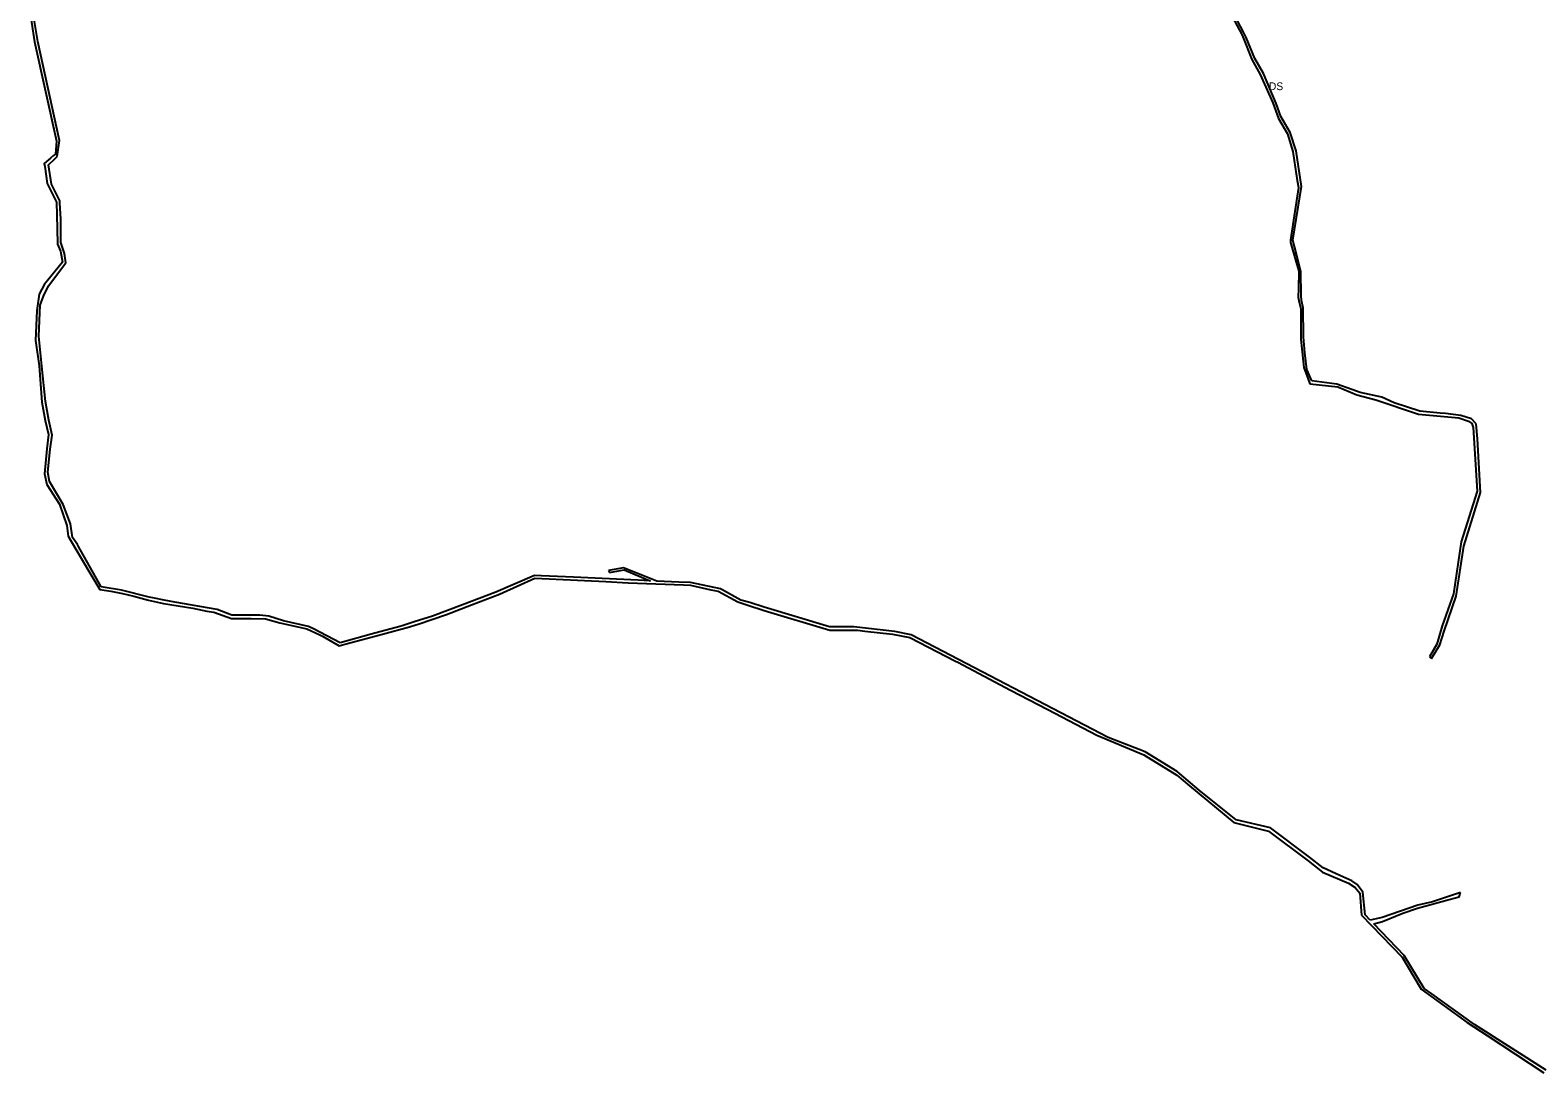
# Model space of a CAD drawing. Extents: x -477304 to -465641, y -1159113 to -1149285.
# Drawn here: x -474185 to -472433, y -1158544 to -1157333 of the extents above; entities that cross this region are included whole.
import ezdxf

# ---------------------------------------------------------------- set-up
doc = ezdxf.new("R2010")
doc.units = 0
doc.layers.add('35', color=7, linetype='Continuous')

msp = doc.modelspace()

# ---------------------------------------------------------------- linework, layer by layer
at = {"layer": '35'}
for p, q in [((-472809, -1157278.8), (-472777.1, -1157338.1)), ((-474184.8, -1157313.7), (-474179.7, -1157346.8)), ((-474175.7, -1157346.4), (-474181.1, -1157313.9)), ((-474150.5, -1157461.2), (-474175.7, -1157346.4)), ((-472777.1, -1157338.1), (-472776, -1157340.8)), ((-472762, -1157366), (-472772.2, -1157341.6)), ((-472752, -1157383.6), (-472762, -1157366)), ((-472737.3, -1157418.4), (-472752, -1157383.6)), ((-472741.4, -1157417.6), (-472736.2, -1157431.5)), ((-472731.8, -1157433.5), (-472737.3, -1157418.4)), ((-472736.2, -1157431.5), (-472734.6, -1157435.7)), ((-474153.3, -1157479.7), (-474150.5, -1157461.2)), ((-474167.8, -1157491.6), (-474165.1, -1157511.4)), ((-474160, -1157511.9), (-474163.3, -1157489.5)), ((-474157.5, -1157478.7), (-474161, -1157481.7)), ((-472716.4, -1157484.5), (-472713.2, -1157507.6)), ((-474165.1, -1157511.4), (-474154.1, -1157532.8)), ((-474149.2, -1157552.7), (-474150.2, -1157533.9)), ((-474149.2, -1157579.6), (-474149.2, -1157552.7)), ((-474144.7, -1157592.4), (-474149.2, -1157579.6)), ((-472716.1, -1157584.6), (-472718, -1157577.1)), ((-474152.9, -1157581.9), (-474149.6, -1157589.8)), ((-474143.3, -1157603.4), (-474144.7, -1157592.4)), ((-472713.4, -1157594.9), (-472716.1, -1157584.6)), ((-472708.7, -1157613.4), (-472713.4, -1157594.9)), ((-474163.5, -1157630.2), (-474143.3, -1157603.4)), ((-472714, -1157602.5), (-472711, -1157613)), ((-472711, -1157613), (-472711.4, -1157633.2)), ((-472708.2, -1157641.2), (-472708.7, -1157613.4)), ((-474169.4, -1157642), (-474163.5, -1157630.2)), ((-474164.3, -1157623.5), (-474167.9, -1157628.3)), ((-472711.4, -1157633.2), (-472711.8, -1157643.2)), ((-474173, -1157652.5), (-474169.4, -1157642)), ((-472711.8, -1157643.2), (-472710.5, -1157649.1)), ((-472710.5, -1157649.1), (-472708.9, -1157657)), ((-472708, -1157647.1), (-472708.2, -1157641.2)), ((-474177.1, -1157658.6), (-474178.5, -1157693.8)), ((-474178.5, -1157693.8), (-474174.4, -1157722.9)), ((-474174.4, -1157722.9), (-474171, -1157765.3)), ((-472698.2, -1157744), (-472665.6, -1157747.5)), ((-472667.1, -1157744.4), (-472695.9, -1157740.5)), ((-472649.7, -1157750.7), (-472667.1, -1157744.4)), ((-474159.1, -1157803.8), (-474163.1, -1157786.1)), ((-472525.2, -1157783.6), (-472513.8, -1157787.5)), ((-472503.5, -1157808), (-472504.9, -1157790.5)), ((-474161.6, -1157819.8), (-474159.1, -1157803.8)), ((-474168.2, -1157848.7), (-474165.2, -1157861)), ((-474165.2, -1157861), (-474150.8, -1157883.7)), ((-474137.7, -1157906.7), (-474146.3, -1157884)), ((-474135.7, -1157922.4), (-474137.7, -1157906.7)), ((-474129.8, -1157930.7), (-474135.7, -1157922.4)), ((-474128.5, -1157933), (-474129.8, -1157930.7)), ((-474102.1, -1157979.9), (-474128.5, -1157933)), ((-473512.9, -1157960.9), (-473511.8, -1157963.3)), ((-474078.8, -1157983.6), (-474102.1, -1157979.9)), ((-474046.5, -1157991.9), (-474078.8, -1157983.6)), ((-473553.6, -1157968.7), (-473590.6, -1157966.9)), ((-473478.5, -1157972.1), (-473553.6, -1157968.7)), ((-473431.4, -1157974.3), (-473456.9, -1157973.4)), ((-473417.8, -1157974.7), (-473431.4, -1157974.3)), ((-474040.4, -1157993.1), (-474046.5, -1157991.9)), ((-474029, -1157995.3), (-474040.4, -1157993.1)), ((-474016.7, -1157997.6), (-474029, -1157995.3)), ((-473967.7, -1158006.3), (-474016.7, -1157997.6)), ((-473682.4, -1158000.9), (-473717.3, -1158013.9)), ((-473643.7, -1157985.9), (-473682.4, -1158000.9)), ((-473348.9, -1157998.2), (-473359.4, -1157995.3)), ((-473332.1, -1158003.6), (-473348.9, -1157998.2)), ((-472531.6, -1157988), (-472544.4, -1158025.1)), ((-473950.5, -1158012.6), (-473967.7, -1158006.3)), ((-473918, -1158012.9), (-473950.5, -1158012.6)), ((-473717.3, -1158013.9), (-473738.6, -1158020.6)), ((-473256.4, -1158026.3), (-473332.1, -1158003.6)), ((-473788.7, -1158035), (-473824.8, -1158045)), ((-473738.6, -1158020.6), (-473752.8, -1158025)), ((-473228, -1158026.2), (-473256.4, -1158026.3)), ((-473180.4, -1158031.7), (-473228, -1158026.2)), ((-472559.4, -1158061.2), (-472557.1, -1158062.9)), ((-472645.6, -1158329.2), (-472643.8, -1158331.6)), ((-472643.8, -1158331.6), (-472640.4, -1158335.9)), ((-472640.4, -1158335.9), (-472638.4, -1158361.4)), ((-472572.7, -1158349.6), (-472614.2, -1158364.1)), ((-472573.2, -1158353.1), (-472536.5, -1158343.1)), ((-472638.4, -1158361.4), (-472591.1, -1158410)), ((-472628.4, -1158366.9), (-472634.1, -1158360.9)), ((-472614.2, -1158364.1), (-472628.4, -1158366.9)), ((-472591.1, -1158410), (-472585, -1158420.7)), ((-472556.7, -1158452.7), (-472565.6, -1158446.3)), ((-472515.5, -1158486.1), (-472492.5, -1158501.2)), ((-472492.5, -1158501.2), (-472426.3, -1158544.5))]:
    msp.add_line(p, q, dxfattribs=at)
for points in [[(-472772.2, -1157341.6), (-472775.2, -1157335.3), (-472805.8, -1157277.4)], [(-474179.7, -1157346.8), (-474154.2, -1157462.2), (-474155.5, -1157477), (-474157.5, -1157478.7)], [(-472776, -1157340.8), (-472765.8, -1157367.3), (-472755.9, -1157384.6), (-472741.4, -1157417.6)], [(-472734.6, -1157435.7), (-472724.3, -1157453.4), (-472717.9, -1157474.1), (-472716.4, -1157484.5)], [(-472714, -1157473.4), (-472721.1, -1157451.9), (-472731.8, -1157433.5)], [(-472718, -1157577.1), (-472707.9, -1157514.8), (-472714, -1157473.4)], [(-474161, -1157481.7), (-474168.3, -1157487.9), (-474167.8, -1157491.6)], [(-474163.3, -1157489.5), (-474156.1, -1157482.4), (-474153.3, -1157479.7)], [(-472713.2, -1157507.6), (-472711.3, -1157515.8), (-472720.9, -1157576.7)], [(-474150.2, -1157533.9), (-474150.4, -1157531.3), (-474160, -1157511.9)], [(-474154.1, -1157532.8), (-474153.3, -1157563.6), (-474152.9, -1157581.9)], [(-472720.9, -1157576.7), (-472720.9, -1157579.8), (-472714, -1157602.5)], [(-474149.6, -1157589.8), (-474147.1, -1157602.7), (-474164.3, -1157623.5)], [(-474167.9, -1157628.3), (-474174.2, -1157639.8), (-474177.1, -1157658.6)], [(-472705.7, -1157689.4), (-472706.1, -1157655.7), (-472708, -1157647.1)], [(-474163.1, -1157786.1), (-474167, -1157764.7), (-474171, -1157723.4), (-474174.7, -1157688.6), (-474173, -1157652.5)], [(-472708.9, -1157657), (-472708.8, -1157692.3), (-472705.4, -1157725.2), (-472700.3, -1157738.5), (-472698.2, -1157744)], [(-472695.9, -1157740.5), (-472701.6, -1157727.3), (-472704.2, -1157707.9), (-472705.7, -1157689.4)], [(-472665.6, -1157747.5), (-472643.8, -1157756.6), (-472621.6, -1157762.7)], [(-472570.5, -1157775.9), (-472600.4, -1157765.9), (-472614.7, -1157759.4), (-472639.7, -1157754.2), (-472649.7, -1157750.7)], [(-474171, -1157765.3), (-474167.4, -1157786.4), (-474163.5, -1157803)], [(-472621.6, -1157762.7), (-472571.9, -1157779.3), (-472525.2, -1157783.6)], [(-472523, -1157780.8), (-472540.8, -1157778.5), (-472546.8, -1157778), (-472570.5, -1157775.9)], [(-472513.8, -1157787.5), (-472510, -1157790.1), (-472508.5, -1157794.9), (-472504, -1157868.7), (-472522.4, -1157927.7), (-472531.6, -1157988)], [(-472504.9, -1157790.5), (-472510.5, -1157784.7), (-472523, -1157780.8)], [(-474163.5, -1157803), (-474165.5, -1157819.4), (-474168.2, -1157848.7)], [(-472542.3, -1158031.2), (-472528.4, -1157990.6), (-472519.5, -1157932.7), (-472500.1, -1157870.3), (-472503.5, -1157808)], [(-474146.3, -1157884), (-474162.3, -1157857.6), (-474164.2, -1157846.8), (-474161.6, -1157819.8)], [(-474150.8, -1157883.7), (-474142, -1157908.4), (-474140.5, -1157920.9), (-474117.6, -1157959.7), (-474104, -1157982.8), (-474091.1, -1157985), (-474077.5, -1157987.4), (-474064.3, -1157990.8), (-474047.2, -1157995.3), (-474030, -1157999), (-473995.9, -1158004.8), (-473979.4, -1158008.1), (-473971.2, -1158009.2), (-473951, -1158016.5)], [(-473456.9, -1157973.4), (-473495.5, -1157957.7), (-473512.9, -1157960.9)], [(-473511.8, -1157963.3), (-473494.9, -1157959.9), (-473464.4, -1157972.7), (-473478.5, -1157972.1)], [(-473951, -1158016.5), (-473928, -1158016.8), (-473911.5, -1158017.1), (-473894.6, -1158021.5), (-473863.3, -1158028.7), (-473848.2, -1158035.6), (-473845.2, -1158037.3), (-473825.8, -1158048.2), (-473817.6, -1158046), (-473775.4, -1158035), (-473744.1, -1158026.2), (-473736.7, -1158024.1), (-473733.9, -1158023.2), (-473701.2, -1158012), (-473671.9, -1158000.8), (-473639.7, -1157988.2), (-473598.4, -1157969.6), (-473516.2, -1157973.8), (-473490.1, -1157975.2), (-473425.7, -1157977.5), (-473417.7, -1157977.9), (-473394.1, -1157983.4), (-473385.6, -1157984.9), (-473362.9, -1157997.4), (-473351.1, -1158001.3), (-473332, -1158007.4), (-473255.7, -1158030.3), (-473227.1, -1158030.3), (-473223.5, -1158030.2), (-473215.3, -1158031.4), (-473183.1, -1158034.9), (-473163.1, -1158038.8), (-473109.8, -1158066), (-473107.3, -1158067.2), (-473046.1, -1158099.7), (-473002.6, -1158122.5), (-472945.9, -1158152.1), (-472891.1, -1158174.9), (-472852.8, -1158198.5), (-472845.6, -1158204.7), (-472837.9, -1158211.2), (-472786.5, -1158253.7), (-472746.4, -1158263.5), (-472700.1, -1158298), (-472683.7, -1158311.3), (-472653.3, -1158323.9), (-472645.6, -1158329.2)], [(-473590.6, -1157966.9), (-473599.1, -1157966.5), (-473643.7, -1157985.9)], [(-473359.4, -1157995.3), (-473382.7, -1157982.1), (-473417.8, -1157974.7)], [(-473824.8, -1158045), (-473855.5, -1158028.7), (-473861.6, -1158025.9), (-473890.5, -1158019.3), (-473907.5, -1158013.8), (-473918, -1158012.9)], [(-473752.8, -1158025), (-473755.5, -1158025.8), (-473788.7, -1158035)], [(-472932.5, -1158154.8), (-473161.4, -1158035.7), (-473180.4, -1158031.7)], [(-472544.4, -1158025.1), (-472550.8, -1158046.5), (-472559.4, -1158061.2)], [(-472557.1, -1158062.9), (-472547.2, -1158047.3), (-472542.3, -1158031.2)], [(-472698.7, -1158293.9), (-472743.9, -1158259.9), (-472783.7, -1158250.4), (-472826.9, -1158215.9), (-472852.4, -1158194.2), (-472889.4, -1158171.5), (-472932.5, -1158154.8)], [(-472663.6, -1158315.1), (-472682.9, -1158306.3), (-472698.7, -1158293.9)], [(-472643.2, -1158325.7), (-472649.5, -1158321.5), (-472663.6, -1158315.1)], [(-472634.1, -1158360.9), (-472636.7, -1158334.4), (-472643.2, -1158325.7)], [(-472523.3, -1158335.1), (-472555.9, -1158345.8), (-472572.7, -1158349.6)], [(-472536.5, -1158343.1), (-472525, -1158340), (-472523.3, -1158335.1)], [(-472624, -1158371.4), (-472613.8, -1158368.6), (-472590.2, -1158359), (-472573.2, -1158353.1)], [(-472565.6, -1158446.3), (-472588.7, -1158408.2), (-472624, -1158371.4)], [(-472585, -1158420.7), (-472568.9, -1158447.4), (-472515.5, -1158486.1)], [(-472423.9, -1158541.5), (-472506.9, -1158488.3), (-472556.7, -1158452.7)]]:
    msp.add_lwpolyline(points, dxfattribs=at)

# ---------------------------------------------------------------- texts
msp.add_text('DS', height=9, dxfattribs=at).set_placement((-472745.9, -1157402.8))

doc.saveas('drawing.dxf')
